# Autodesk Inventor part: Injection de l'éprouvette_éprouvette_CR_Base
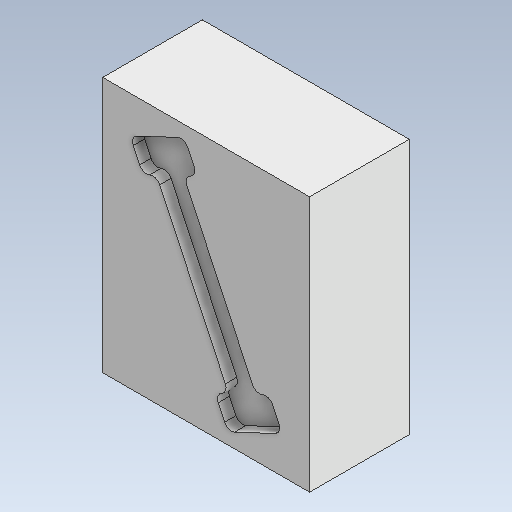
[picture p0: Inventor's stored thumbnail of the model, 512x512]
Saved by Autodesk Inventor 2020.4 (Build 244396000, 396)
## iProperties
Created: 2021-10
Part Number: Injection de l'éprouvette_éprouvette_CR_Base
Material: Générique
Document SubType Name: Modeling
Designer: mel
Density: 1 g/cm^3
Appearance: Par défaut
Author: mel
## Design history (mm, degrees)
node "Injection de l'éprouvette_éprouvette_MP"
feature "Solide3::Injection de l'éprouvette_éprouvette_MP"
tag "FonctionRepérage1"
node "Solide1"
feature "Injection de l'éprouvette_éprouvette_MP_Corps"
